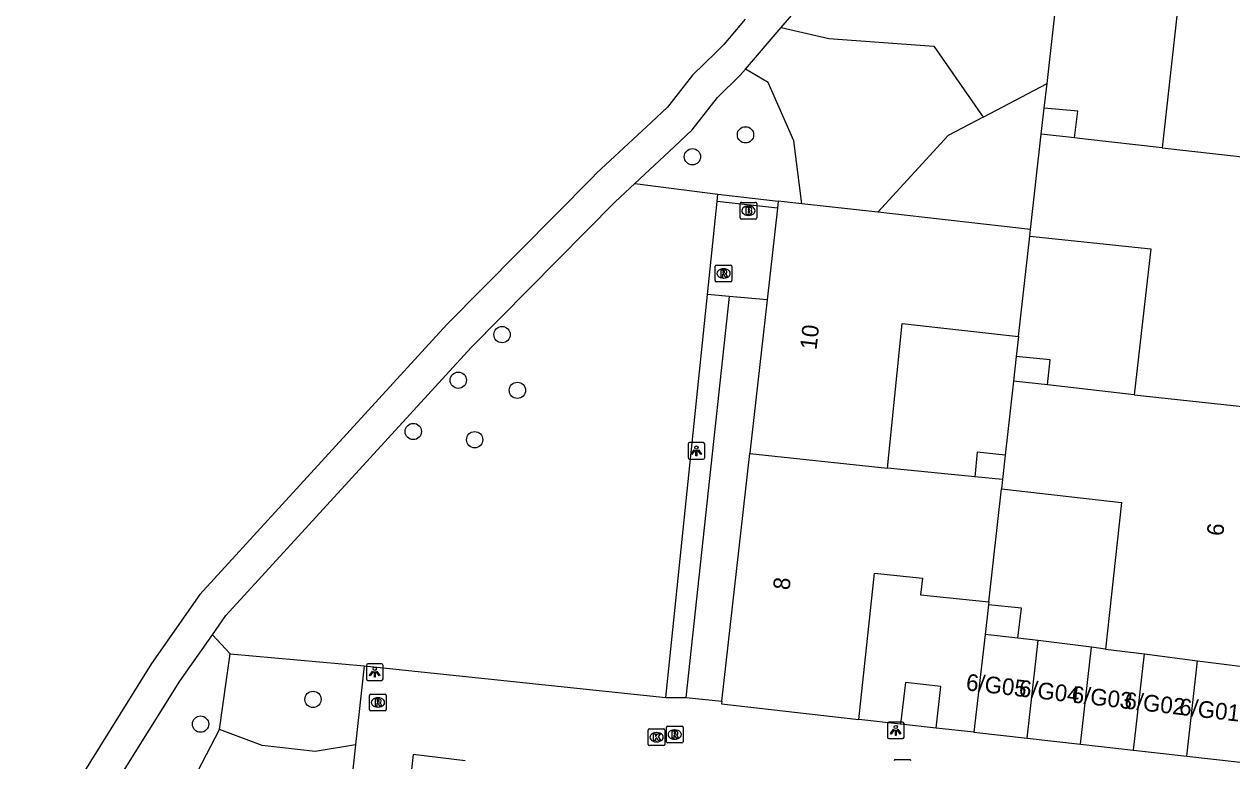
# Model space of a CAD drawing. Extents: x 162398 to 163643, y 386453 to 387397.
# Drawn here: x 162436.4 to 162508.8, y 386537.1 to 386581.3 of the extents above; entities that cross this region are included whole.
import ezdxf

# ---------------------------------------------------------------- set-up
doc = ezdxf.new("R2010")
doc.units = 0
for name, color, linetype in [('IMGEO_Boom', 7, 'Continuous'), ('IMGEO_Brandkraan', 7, 'Continuous'), ('IMGEO_Erf', 7, 'Continuous'), ('IMGEO_Groenvoorziening', 7, 'Continuous'), ('IMGEO_Kolk', 7, 'Continuous'), ('IMGEO_Lichtpunt', 7, 'Continuous'), ('IMGEO_Meer_plas_ven_vijver', 7, 'Continuous'), ('IMGEO_Muur', 7, 'Continuous'), ('IMGEO_Pand', 7, 'Continuous'), ('IMGEO_Pand_nummerreeks', 7, 'Continuous'), ('IMGEO_Parkeervlak_open', 7, 'Continuous'), ('IMGEO_Rioolput', 7, 'Continuous'), ('IMGEO_Voetpad_open', 7, 'Continuous')]:
    doc.layers.add(name, color=color, linetype=linetype)

msp = doc.modelspace()

# ---------------------------------------------------------------- linework, layer by layer
at = {"layer": 'IMGEO_Boom'}
for centre in [(162479.639, 386574.623), (162476.459, 386573.308), (162465.046, 386562.65), (162462.422, 386559.917), (162465.964, 386559.309), (162459.721, 386556.841), (162463.403, 386556.347), (162453.712, 386540.782), (162446.969, 386539.3)]:
    msp.add_circle(centre, 0.489, dxfattribs=at)
at = {"layer": 'IMGEO_Brandkraan'}
for p, q in [((162479.316, 386569.651), (162479.316, 386570.503)), ((162479.391, 386570.577), (162480.243, 386570.577)), ((162479.804, 386570.357), (162479.829, 386570.357)), ((162480.317, 386570.503), (162480.317, 386569.651)), ((162480.243, 386569.577), (162479.391, 386569.577)), ((162479.827, 386569.797), (162479.802, 386569.797))]:
    msp.add_line(p, q, dxfattribs=at)
for points in [[(162479.316, 386569.651), (162479.316, 386570.503)], [(162479.391, 386570.577), (162480.243, 386570.577)], [(162479.664, 386570.277), (162479.664, 386569.877), (162479.877, 386569.877)], [(162479.895, 386570.277), (162479.664, 386570.277)], [(162479.843, 386570.196), (162479.789, 386570.196), (162479.789, 386570.12)], [(162479.789, 386570.12), (162479.842, 386570.12)], [(162479.851, 386570.044), (162479.789, 386570.044), (162479.789, 386569.963)], [(162479.789, 386569.963), (162479.851, 386569.963)], [(162480.317, 386570.503), (162480.317, 386569.651)], [(162480.243, 386569.577), (162479.391, 386569.577)]]:
    msp.add_lwpolyline(points, dxfattribs=at)
for centre, radius, start, end in [((162479.393, 386570.501), 0.0765, 91.55205, 178.44795), ((162479.393, 386570.501), 0.0765, 91.55205, 178.44795), ((162479.844, 386570.158), 0.0379, 267.82845, 90.93552), ((162479.852, 386570.003), 0.0404, 269.87594, 90.50774), ((162479.899, 386570.132), 0.145, 59.4692, 91.53667), ((162479.924, 386570.179), 0.0922, 285.51372, 58.15012), ((162479.929, 386569.987), 0.105, 301.31148, 78.98903), ((162480.241, 386570.501), 0.0765, 1.55205, 88.44795), ((162480.241, 386570.501), 0.0765, 1.55205, 88.44795), ((162479.393, 386569.653), 0.0765, 181.55205, 268.44795), ((162479.393, 386569.653), 0.0765, 181.55205, 268.44795), ((162479.883, 386570.128), 0.251, 268.66757, 293.53466), ((162480.241, 386569.653), 0.0765, 271.55205, 358.44795), ((162480.241, 386569.653), 0.0765, 271.55205, 358.44795)]:
    msp.add_arc(centre, radius, start, end, dxfattribs=at)
for centre, major_axis, ratio, start_param, end_param in [((162479.803, 386570.077), (-0.387, 0.002), 0.722429, 4.712389, 7.853982), ((162479.828, 386570.077), (-0.39, 0.002), 0.717154, 1.570796, 4.712389)]:
    msp.add_ellipse(centre, major_axis=major_axis, ratio=ratio, start_param=start_param, end_param=end_param, dxfattribs=at)
at = {"layer": 'IMGEO_Erf'}
for points in [[(162496.006, 386562.526), (162495.871, 386561.33)], [(162494.217, 386546.637), (162494.197, 386546.457)]]:
    msp.add_lwpolyline(points, dxfattribs=at)
at = {"layer": 'IMGEO_Groenvoorziening'}
for points in [[(162481.784, 386581.057), (162483.154, 386582.652), (162490.031, 386589.442)], [(162497.713, 386577.696), (162498.341, 386583.274)], [(162479.631, 386578.553), (162481.784, 386581.057)], [(162481.784, 386581.057), (162484.642, 386580.4), (162490.934, 386579.934), (162493.882, 386575.678)], [(162473.002, 386571.704), (162475.355, 386573.9), (162476.447, 386574.92), (162477.958, 386576.855), (162479.327, 386578.199), (162479.631, 386578.553)], [(162483.023, 386570.497), (162482.544, 386574.265), (162480.991, 386577.76), (162479.631, 386578.553)], [(162493.882, 386575.678), (162497.713, 386577.696)], [(162497.548, 386576.227), (162497.713, 386577.696)], [(162493.882, 386575.678), (162491.789, 386574.576), (162487.578, 386569.984)], [(162447.678, 386544.657), (162448.492, 386545.815), (162463.19, 386561.877), (162471.82, 386570.601), (162473.002, 386571.704)], [(162473.002, 386571.704), (162477.99, 386571.063)], [(162436.396, 386525.055), (162438.347, 386528.973), (162439.081, 386530.869), (162440.223, 386533.06), (162445.726, 386541.877), (162447.678, 386544.657)], [(162448.752, 386543.51), (162447.678, 386544.657)], [(162448.106, 386538.987), (162448.752, 386543.51)], [(162448.752, 386543.51), (162456.771, 386542.788)], [(162436.396, 386525.055), (162439.87, 386523.156), (162448.106, 386538.987)], [(162456.255, 386538.063), (162453.833, 386537.665), (162450.665, 386538.022), (162448.106, 386538.987)]]:
    msp.add_lwpolyline(points, dxfattribs=at)
at = {"layer": 'IMGEO_Kolk'}
for p, q in [((162473.806, 386538.088), (162473.806, 386538.94)), ((162473.881, 386539.014), (162474.733, 386539.014)), ((162474.807, 386538.94), (162474.807, 386538.088)), ((162474.317, 386538.234), (162474.292, 386538.234)), ((162474.294, 386538.794), (162474.319, 386538.794)), ((162474.733, 386538.014), (162473.881, 386538.014)), ((162488.624, 386537.175), (162489.476, 386537.175))]:
    msp.add_line(p, q, dxfattribs=at)
for points in [[(162473.806, 386538.088), (162473.806, 386538.94)], [(162473.881, 386539.014), (162474.733, 386539.014)], [(162474.807, 386538.94), (162474.807, 386538.088)], [(162474.127, 386538.714), (162474.25, 386538.714), (162474.25, 386538.563), (162474.38, 386538.714), (162474.544, 386538.714), (162474.398, 386538.563), (162474.551, 386538.314), (162474.399, 386538.314), (162474.314, 386538.478), (162474.25, 386538.411), (162474.25, 386538.314), (162474.127, 386538.314), (162474.127, 386538.714)], [(162474.733, 386538.014), (162473.881, 386538.014)], [(162488.624, 386537.175), (162489.476, 386537.175)]]:
    msp.add_lwpolyline(points, dxfattribs=at)
for centre, start, end in [((162473.883, 386538.938), 91.55205, 178.44795), ((162473.883, 386538.938), 91.55205, 178.44795), ((162474.731, 386538.938), 1.55205, 88.44795), ((162474.731, 386538.938), 1.55205, 88.44795), ((162473.883, 386538.09), 181.55205, 268.44795), ((162473.883, 386538.09), 181.55205, 268.44795), ((162474.731, 386538.09), 271.55205, 358.44795), ((162474.731, 386538.09), 271.55205, 358.44795), ((162488.626, 386537.099), 91.55205, 178.44795), ((162488.626, 386537.099), 91.55205, 178.44795), ((162489.474, 386537.099), 1.55205, 88.44795), ((162489.474, 386537.099), 1.55205, 88.44795)]:
    msp.add_arc(centre, 0.0765, start, end, dxfattribs=at)
for centre, major_axis, ratio, start_param, end_param in [((162474.293, 386538.514), (-0.387, 0.002), 0.722429, 4.712389, 7.853982), ((162474.318, 386538.514), (-0.39, 0.002), 0.717154, 1.570796, 4.712389)]:
    msp.add_ellipse(centre, major_axis=major_axis, ratio=ratio, start_param=start_param, end_param=end_param, dxfattribs=at)
at = {"layer": 'IMGEO_Lichtpunt'}
for p, q in [((162476.195, 386556.084), (162476.195, 386555.277)), ((162476.195, 386556.084), (162476.195, 386555.277)), ((162477.097, 386556.179), (162476.289, 386556.179)), ((162477.097, 386556.179), (162476.289, 386556.179)), ((162477.191, 386555.277), (162477.191, 386556.084)), ((162477.191, 386555.277), (162477.191, 386556.084)), ((162476.289, 386555.183), (162477.097, 386555.183)), ((162476.289, 386555.183), (162477.097, 386555.183)), ((162456.913, 386542.822), (162456.913, 386542.015)), ((162456.913, 386542.822), (162456.913, 386542.015)), ((162457.815, 386542.917), (162457.007, 386542.917)), ((162457.815, 386542.917), (162457.007, 386542.917)), ((162457.909, 386542.015), (162457.909, 386542.822)), ((162457.909, 386542.015), (162457.909, 386542.822)), ((162457.007, 386541.921), (162457.815, 386541.921)), ((162457.007, 386541.921), (162457.815, 386541.921)), ((162488.145, 386539.332), (162488.145, 386538.525)), ((162488.145, 386539.332), (162488.145, 386538.525)), ((162489.047, 386539.427), (162488.239, 386539.427)), ((162489.047, 386539.427), (162488.239, 386539.427)), ((162489.141, 386538.525), (162489.141, 386539.332)), ((162489.141, 386538.525), (162489.141, 386539.332)), ((162488.239, 386538.431), (162489.047, 386538.431)), ((162488.239, 386538.431), (162489.047, 386538.431))]:
    msp.add_line(p, q, dxfattribs=at)
for points in [[(162476.569, 386555.748), (162476.608, 386555.72), (162476.42, 386555.458), (162476.382, 386555.485), (162476.569, 386555.748)], [(162476.671, 386555.7), (162476.718, 386555.7), (162476.718, 386555.378), (162476.671, 386555.378), (162476.671, 386555.7)], [(162476.781, 386555.72), (162476.819, 386555.747), (162477.006, 386555.485), (162476.967, 386555.457), (162476.781, 386555.72)], [(162457.287, 386542.486), (162457.326, 386542.458), (162457.138, 386542.196), (162457.1, 386542.223), (162457.287, 386542.486)], [(162457.499, 386542.458), (162457.537, 386542.485), (162457.724, 386542.223), (162457.685, 386542.195), (162457.499, 386542.458)], [(162457.389, 386542.438), (162457.436, 386542.438), (162457.436, 386542.116), (162457.389, 386542.116), (162457.389, 386542.438)], [(162488.519, 386538.996), (162488.558, 386538.968), (162488.37, 386538.706), (162488.332, 386538.733), (162488.519, 386538.996)], [(162488.621, 386538.948), (162488.668, 386538.948), (162488.668, 386538.626), (162488.621, 386538.626), (162488.621, 386538.948)], [(162488.731, 386538.968), (162488.769, 386538.995), (162488.956, 386538.733), (162488.917, 386538.705), (162488.731, 386538.968)]]:
    msp.add_lwpolyline(points, dxfattribs=at)
for centre in [(162476.694, 386555.882), (162457.412, 386542.62), (162488.644, 386539.13)]:
    msp.add_circle(centre, 0.0994, dxfattribs=at)
for centre, start, end in [((162476.289, 386556.084), 90, 180), ((162476.289, 386556.084), 90, 180), ((162477.097, 386556.084), 0, 90), ((162477.097, 386556.084), 0, 90), ((162476.289, 386555.277), 180, 270), ((162476.289, 386555.277), 180, 270), ((162477.097, 386555.277), 270, 0), ((162477.097, 386555.277), 270, 360), ((162457.007, 386542.822), 90, 180), ((162457.007, 386542.822), 90, 180), ((162457.815, 386542.822), 0, 90), ((162457.815, 386542.822), 0, 90), ((162457.007, 386542.015), 180, 270), ((162457.007, 386542.015), 180, 270), ((162457.815, 386542.015), 270, 0), ((162457.815, 386542.015), 270, 360), ((162488.239, 386539.332), 90, 180), ((162488.239, 386539.332), 90, 180), ((162489.047, 386539.332), 0, 90), ((162489.047, 386539.332), 0, 90), ((162488.239, 386538.525), 180, 270), ((162488.239, 386538.525), 180, 270), ((162489.047, 386538.525), 270, 0), ((162489.047, 386538.525), 270, 360)]:
    msp.add_arc(centre, 0.0946, start, end, dxfattribs=at)
at = {"layer": 'IMGEO_Meer_plas_ven_vijver'}
msp.add_lwpolyline([(162479.62, 386581.555), (162478.343, 386580.036), (162477.875, 386579.576), (162476.463, 386578.19), (162474.969, 386576.277), (162473.991, 386575.369), (162470.706, 386572.318), (162470.426, 386572.035), (162461.741, 386563.256), (162446.93, 386547.07), (162444.028, 386542.939), (162438.485, 386534.053)], dxfattribs=at)
at = {"layer": 'IMGEO_Muur'}
for points in [[(162477.942, 386570.635), (162477.99, 386571.063)], [(162477.99, 386571.063), (162481.6, 386570.657)], [(162481.552, 386570.229), (162477.942, 386570.635)]]:
    msp.add_lwpolyline(points, dxfattribs=at)
at = {"layer": 'IMGEO_Pand'}
for points in [[(162498.341, 386583.274), (162505.578, 386582.473), (162504.608, 386573.852)], [(162497.372, 386574.664), (162497.548, 386576.227)], [(162499.357, 386574.441), (162499.553, 386576.04), (162497.548, 386576.227)], [(162496.729, 386568.955), (162497.372, 386574.664)], [(162499.357, 386574.441), (162497.372, 386574.664)], [(162504.608, 386573.852), (162500, 386574.369), (162499.357, 386574.441)], [(162504.608, 386573.852), (162513.322, 386572.875)], [(162481.552, 386570.229), (162480.934, 386564.737)], [(162481.6, 386570.657), (162481.552, 386570.229)], [(162483.023, 386570.497), (162481.6, 386570.657)], [(162487.578, 386569.984), (162483.023, 386570.497)], [(162496.729, 386568.955), (162487.578, 386569.984)], [(162496.006, 386562.526), (162496.683, 386568.546)], [(162496.683, 386568.546), (162496.729, 386568.955)], [(162496.683, 386568.546), (162503.942, 386567.785), (162502.946, 386559.035)], [(162480.934, 386564.737), (162479.924, 386555.748), (162479.898, 386555.517)], [(162488.158, 386554.649), (162489.038, 386563.318), (162496.006, 386562.526)], [(162495.871, 386561.33), (162495.706, 386559.86)], [(162497.743, 386559.631), (162497.906, 386561.139), (162495.871, 386561.33)], [(162495.706, 386559.86), (162495.206, 386555.423)], [(162497.743, 386559.631), (162495.706, 386559.86)], [(162502.946, 386559.035), (162497.743, 386559.631)], [(162502.946, 386559.035), (162511.659, 386558.094)], [(162478.229, 386540.682), (162479.898, 386555.517)], [(162479.898, 386555.517), (162488.158, 386554.649)], [(162495.206, 386555.423), (162493.522, 386555.61), (162493.378, 386554.123)], [(162495.206, 386555.423), (162495.041, 386553.955)], [(162493.378, 386554.123), (162488.158, 386554.649)], [(162495.041, 386553.955), (162493.378, 386554.123)], [(162494.217, 386546.637), (162494.98, 386553.411)], [(162495.041, 386553.955), (162494.98, 386553.411)], [(162494.98, 386553.411), (162502.181, 386552.582), (162501.224, 386543.8)], [(162486.439, 386539.585), (162487.376, 386548.346), (162490.24, 386548.042), (162490.138, 386547.051), (162494.217, 386546.637)], [(162494.197, 386546.457), (162493.997, 386544.683)], [(162495.963, 386544.462), (162496.178, 386546.251), (162494.197, 386546.457)], [(162493.997, 386544.683), (162493.336, 386538.81)], [(162495.963, 386544.462), (162493.997, 386544.683)], [(162497.185, 386544.309), (162495.963, 386544.462)], [(162496.527, 386538.451), (162497.185, 386544.309)], [(162500.371, 386543.907), (162497.185, 386544.309)], [(162499.717, 386538.092), (162500.371, 386543.907)], [(162501.224, 386543.8), (162500.371, 386543.907)], [(162501.224, 386543.8), (162503.557, 386543.507)], [(162502.907, 386537.733), (162503.557, 386543.507)], [(162503.557, 386543.507), (162506.743, 386543.105)], [(162506.098, 386537.374), (162506.743, 386543.105)], [(162506.743, 386543.105), (162509.928, 386542.705)], [(162491.064, 386539.065), (162491.346, 386541.567), (162489.222, 386541.794), (162488.923, 386539.306)], [(162478.229, 386540.682), (162478.21, 386540.51), (162486.439, 386539.585)], [(162491.064, 386539.065), (162488.923, 386539.306)], [(162493.336, 386538.81), (162496.527, 386538.451)], [(162496.527, 386538.451), (162499.717, 386538.092)], [(162499.717, 386538.092), (162502.907, 386537.733)], [(162502.907, 386537.733), (162506.098, 386537.374)], [(162506.098, 386537.374), (162509.288, 386537.015)]]:
    msp.add_lwpolyline(points, dxfattribs=at)
at = {"layer": 'IMGEO_Parkeervlak_open'}
for points in [[(162477.363, 386565.052), (162477.942, 386570.635)], [(162480.934, 386564.737), (162478.659, 386564.938)]]:
    msp.add_lwpolyline(points, dxfattribs=at)
at = {"layer": 'IMGEO_Rioolput'}
for p, q in [((162477.827, 386565.89), (162477.827, 386566.742)), ((162477.902, 386566.816), (162478.754, 386566.816)), ((162478.315, 386566.596), (162478.34, 386566.596)), ((162478.828, 386566.742), (162478.828, 386565.89)), ((162478.754, 386565.816), (162477.902, 386565.816)), ((162478.338, 386566.036), (162478.313, 386566.036)), ((162457.104, 386540.173), (162457.104, 386541.025)), ((162457.179, 386541.099), (162458.031, 386541.099)), ((162458.105, 386541.025), (162458.105, 386540.173)), ((162457.615, 386540.319), (162457.59, 386540.319)), ((162457.592, 386540.879), (162457.617, 386540.879)), ((162458.031, 386540.099), (162457.179, 386540.099)), ((162474.893, 386538.248), (162474.893, 386539.1)), ((162474.968, 386539.174), (162475.82, 386539.174)), ((162475.381, 386538.954), (162475.406, 386538.954)), ((162475.894, 386539.1), (162475.894, 386538.248)), ((162475.82, 386538.174), (162474.968, 386538.174)), ((162475.404, 386538.394), (162475.379, 386538.394))]:
    msp.add_line(p, q, dxfattribs=at)
for points in [[(162477.827, 386565.89), (162477.827, 386566.742)], [(162477.902, 386566.816), (162478.754, 386566.816)], [(162478.416, 386566.514), (162478.164, 386566.516), (162478.164, 386566.116)], [(162478.342, 386566.435), (162478.288, 386566.435), (162478.288, 386566.354)], [(162478.288, 386566.354), (162478.34, 386566.354)], [(162478.828, 386566.742), (162478.828, 386565.89)], [(162478.754, 386565.816), (162477.902, 386565.816)], [(162478.164, 386566.116), (162478.288, 386566.116), (162478.288, 386566.278), (162478.299, 386566.278)], [(162478.346, 386566.249), (162478.417, 386566.116), (162478.557, 386566.116), (162478.492, 386566.242)], [(162457.104, 386540.173), (162457.104, 386541.025)], [(162457.179, 386541.099), (162458.031, 386541.099)], [(162458.105, 386541.025), (162458.105, 386540.173)], [(162457.693, 386540.797), (162457.441, 386540.799), (162457.441, 386540.399)], [(162457.441, 386540.399), (162457.565, 386540.399), (162457.565, 386540.561), (162457.576, 386540.561)], [(162457.619, 386540.718), (162457.565, 386540.718), (162457.565, 386540.637)], [(162457.565, 386540.637), (162457.617, 386540.637)], [(162457.623, 386540.532), (162457.694, 386540.399), (162457.834, 386540.399), (162457.769, 386540.525)], [(162458.031, 386540.099), (162457.179, 386540.099)], [(162474.893, 386538.248), (162474.893, 386539.1)], [(162474.968, 386539.174), (162475.82, 386539.174)], [(162475.482, 386538.872), (162475.23, 386538.874), (162475.23, 386538.474)], [(162475.894, 386539.1), (162475.894, 386538.248)], [(162475.82, 386538.174), (162474.968, 386538.174)], [(162475.23, 386538.474), (162475.354, 386538.474), (162475.354, 386538.636), (162475.365, 386538.636)], [(162475.408, 386538.793), (162475.354, 386538.793), (162475.354, 386538.712)], [(162475.354, 386538.712), (162475.406, 386538.712)], [(162475.412, 386538.607), (162475.483, 386538.474), (162475.623, 386538.474), (162475.558, 386538.6)]]:
    msp.add_lwpolyline(points, dxfattribs=at)
for centre, radius, start, end in [((162477.904, 386566.74), 0.0765, 91.55205, 178.44795), ((162477.904, 386566.74), 0.0765, 91.55205, 178.44795), ((162478.324, 386566.543), 0.19, 274.7715, 282.96867), ((162478.348, 386566.339), 0.0964, 77.00612, 93.18647), ((162478.362, 386566.396), 0.0378, 276.66336, 79.67722), ((162478.415, 386566.404), 0.109, 350.36119, 89.41601), ((162478.413, 386566.404), 0.112, 277.58423, 350.98172), ((162478.752, 386566.74), 0.0765, 1.55205, 88.44795), ((162478.752, 386566.74), 0.0765, 1.55205, 88.44795), ((162477.904, 386565.892), 0.0765, 181.55205, 268.44795), ((162477.904, 386565.892), 0.0765, 181.55205, 268.44795), ((162478.298, 386566.225), 0.0533, 26.02933, 88.69889), ((162478.397, 386566.189), 0.108, 29.51342, 73.79051), ((162478.752, 386565.892), 0.0765, 271.55205, 358.44795), ((162478.752, 386565.892), 0.0765, 271.55205, 358.44795), ((162457.181, 386541.023), 0.0765, 91.55205, 178.44795), ((162457.181, 386541.023), 0.0765, 91.55205, 178.44795), ((162458.029, 386541.023), 0.0765, 1.55205, 88.44795), ((162458.029, 386541.023), 0.0765, 1.55205, 88.44795), ((162457.575, 386540.508), 0.0533, 26.02933, 88.69889), ((162457.601, 386540.826), 0.19, 274.7715, 282.96867), ((162457.625, 386540.622), 0.0964, 77.00612, 93.18647), ((162457.639, 386540.679), 0.0378, 276.66336, 79.67722), ((162457.692, 386540.687), 0.109, 350.36119, 89.41601), ((162457.69, 386540.687), 0.112, 277.58423, 350.98172), ((162457.674, 386540.472), 0.108, 29.51342, 73.79051), ((162457.181, 386540.175), 0.0765, 181.55205, 268.44795), ((162457.181, 386540.175), 0.0765, 181.55205, 268.44795), ((162458.029, 386540.175), 0.0765, 271.55205, 358.44795), ((162458.029, 386540.175), 0.0765, 271.55205, 358.44795), ((162474.97, 386539.098), 0.0765, 91.55205, 178.44795), ((162474.97, 386539.098), 0.0765, 91.55205, 178.44795), ((162475.481, 386538.762), 0.109, 350.36119, 89.41601), ((162475.818, 386539.098), 0.0765, 1.55205, 88.44795), ((162475.818, 386539.098), 0.0765, 1.55205, 88.44795), ((162474.97, 386538.25), 0.0765, 181.55205, 268.44795), ((162474.97, 386538.25), 0.0765, 181.55205, 268.44795), ((162475.364, 386538.583), 0.0533, 26.02933, 88.69889), ((162475.39, 386538.901), 0.19, 274.7715, 282.96867), ((162475.414, 386538.697), 0.0964, 77.00612, 93.18647), ((162475.428, 386538.754), 0.0378, 276.66336, 79.67722), ((162475.479, 386538.762), 0.112, 277.58423, 350.98172), ((162475.463, 386538.547), 0.108, 29.51342, 73.79051), ((162475.818, 386538.25), 0.0765, 271.55205, 358.44795), ((162475.818, 386538.25), 0.0765, 271.55205, 358.44795)]:
    msp.add_arc(centre, radius, start, end, dxfattribs=at)
for centre, major_axis, ratio, start_param, end_param in [((162478.314, 386566.316), (-0.387, 0.002), 0.722429, 4.712389, 7.853982), ((162478.339, 386566.316), (-0.39, 0.002), 0.717154, 1.570796, 4.712389), ((162457.591, 386540.599), (-0.387, 0.002), 0.722429, 4.712389, 7.853982), ((162457.616, 386540.599), (-0.39, 0.002), 0.717154, 1.570796, 4.712389), ((162475.38, 386538.674), (-0.387, 0.002), 0.722429, 4.712389, 7.853982), ((162475.405, 386538.674), (-0.39, 0.002), 0.717154, 1.570796, 4.712389)]:
    msp.add_ellipse(centre, major_axis=major_axis, ratio=ratio, start_param=start_param, end_param=end_param, dxfattribs=at)
at = {"layer": 'IMGEO_Voetpad_open'}
for points in [[(162474.859, 386540.892), (162477.363, 386565.052)], [(162478.659, 386564.938), (162476.066, 386540.905)], [(162478.659, 386564.938), (162477.363, 386565.052)], [(162456.771, 386542.788), (162456.255, 386538.063)], [(162456.771, 386542.788), (162474.859, 386540.892)], [(162474.859, 386540.892), (162476.066, 386540.905)], [(162476.066, 386540.905), (162478.229, 386540.682)], [(162488.923, 386539.306), (162486.439, 386539.585)], [(162493.336, 386538.81), (162491.064, 386539.065)], [(162456.255, 386538.063), (162452.109, 386499.982), (162450.572, 386485.975)], [(162462.829, 386537.098), (162459.71, 386537.473), (162455.514, 386500), (162454.691, 386492.655)]]:
    msp.add_lwpolyline(points, dxfattribs=at)

# ---------------------------------------------------------------- texts
at = {"layer": 'IMGEO_Pand_nummerreeks'}
for s, rotation, p in [('10', 83.58308, (162483.894, 386561.705)), ('6', 83.58308, (162508.274, 386550.545)), ('8', 83.58308, (162482.274, 386547.304)), ('6/G05', 353.4339, (162492.822, 386541.335)), ('6/G04', 353.4339, (162495.989, 386540.97)), ('6/G03', 353.4339, (162499.155, 386540.606)), ('6/G02', 353.4339, (162502.316, 386540.242)), ('6/G01', 353.4339, (162505.598, 386539.864))]:
    msp.add_text(s, height=1, rotation=rotation, dxfattribs=at).set_placement(p)

doc.saveas('drawing.dxf')
